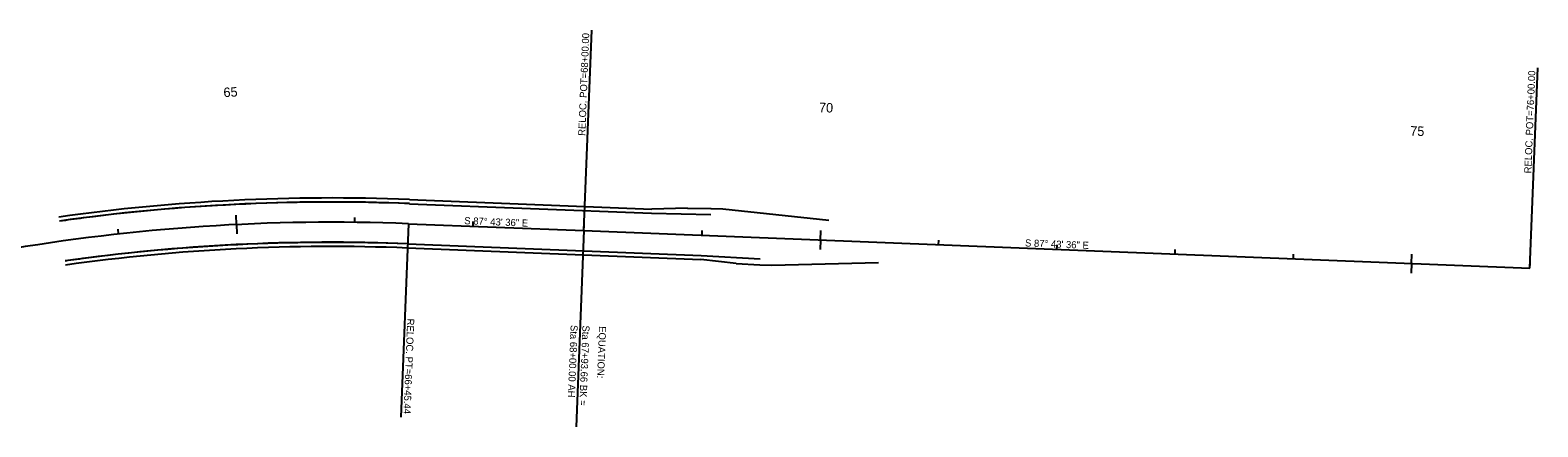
# Model space of a CAD drawing. Extents: x 1966701 to 1969286, y 1117441 to 1118086.
# Drawn here: x 1968012 to 1969286, y 1117751 to 1118086 of the extents above; entities that cross this region are included whole.
import ezdxf

# ---------------------------------------------------------------- set-up
doc = ezdxf.new("R2010")
doc.units = 0
for name, color, linetype in [('Level 19', 7, 'Continuous'), ('Level 27', 7, 'Continuous'), ('Level 35', 7, 'Continuous'), ('Level 39', 7, 'Continuous')]:
    doc.layers.add(name, color=color, linetype=linetype)

msp = doc.modelspace()

# ---------------------------------------------------------------- linework, layer by layer
at = {"layer": 'Level 19'}
for p, q in [((1968186.2, 1117921.9), (1968185.8, 1117929.9)), ((1968286.1, 1117923.7), (1968286.2, 1117927.7)), ((1968086.5, 1117913.9), (1968086, 1117917.9)), ((1968186.2, 1117921.9), (1968186.5, 1117913.9)), ((1968331.5, 1117922.6), (1968479.6, 1117916.7)), ((1968386.1, 1117920.4), (1968386.2, 1117924.4)), ((1968479.6, 1117916.7), (1968479.8, 1117920.7)), ((1968479.6, 1117916.7), (1969279, 1117884.9)), ((1968579.6, 1117912.7), (1968579.7, 1117916.7)), ((1968679.5, 1117908.7), (1968679.8, 1117916.7)), ((1968679.5, 1117908.7), (1968679.2, 1117900.8)), ((1968779.4, 1117904.8), (1968779.6, 1117908.8)), ((1968879.3, 1117900.8), (1968879.5, 1117904.8)), ((1968979.3, 1117896.8), (1968979.4, 1117900.8)), ((1969079.2, 1117892.9), (1969079.3, 1117896.9)), ((1969179.1, 1117888.9), (1969179.4, 1117896.9)), ((1969179.1, 1117888.9), (1969178.8, 1117880.9)), ((1969279, 1117884.9), (1969279.2, 1117888.9))]:
    msp.add_line(p, q, dxfattribs=at)
msp.add_arc((1968266.6, 1116286.8), 1637, 87.7266, 111.9958, dxfattribs=at)
at = {"layer": 'Level 27'}
for p, q in [((1968332.2, 1117939.5), (1968536.9, 1117931.4)), ((1968536.9, 1117931.4), (1968586.9, 1117930.4)), ((1968330.9, 1117905.6), (1968578.7, 1117895.7)), ((1968578.7, 1117895.7), (1968628.6, 1117892.8))]:
    msp.add_line(p, q, dxfattribs=at)
for radius, start, end in [(1654.1, 87.7266, 97.9969), (1654, 87.7266, 97.2969), (1654, 97.2969, 97.9969), (1620.1, 87.7266, 97.9969), (1620, 87.7266, 97.2969), (1620, 97.2969, 97.9969)]:
    msp.add_arc((1968266.6, 1116286.8), radius, start, end, dxfattribs=at)
at = {"layer": 'Level 35'}
for p, q in [((1968332.4, 1117943), (1968537, 1117934.9)), ((1968567.1, 1117935.8), (1968537, 1117934.9)), ((1968567.1, 1117935.8), (1968587, 1117935.4)), ((1968587.1, 1117935.4), (1968597.1, 1117935)), ((1968597.1, 1117935), (1968686.7, 1117925.5)), ((1968330.7, 1117902.1), (1968578.6, 1117892.2)), ((1968608.4, 1117888.9), (1968578.6, 1117892.2)), ((1968638.4, 1117887.4), (1968728.6, 1117889.8)), ((1968608.4, 1117888.9), (1968628.3, 1117887.8)), ((1968628.4, 1117887.8), (1968638.4, 1117887.4))]:
    msp.add_line(p, q, dxfattribs=at)
for radius in [1657.5, 1616.5]:
    msp.add_arc((1968266.6, 1116286.8), radius, 87.7266, 97.9969, dxfattribs=at)
at = {"layer": 'Level 39'}
for p, q in [((1968479.6, 1117916.7), (1968486.4, 1118086.1)), ((1969279, 1117884.9), (1969285.7, 1118054.4)), ((1968331.5, 1117922.6), (1968325.1, 1117759.1)), ((1968479.6, 1117916.7), (1968473.1, 1117750.9))]:
    msp.add_line(p, q, dxfattribs=at)

# ---------------------------------------------------------------- texts
at = {"layer": 'Level 19'}
for s, rotation, p in [('65', 2.8171, (1968175.3, 1118029.5)), ('70', 357.7266, (1968678.2, 1118016.9)), ('75', 357.7266, (1969177.8, 1117997.1))]:
    msp.add_text(s, height=8, rotation=rotation, dxfattribs=at).set_placement(p)
at = {"layer": 'Level 39'}
for s, rotation, p in [('RELOC. POT=68+00.00', 87.7266, (1968480.8, 1117996.7)), ('RELOC. POT=76+00.00', 87.7266, (1969280.2, 1117965)), ('S 87%%d 43\' 36" E', 357.7266, (1968378.5, 1117922.2)), ('S 87%%d 43\' 36" E', 357.7266, (1968852.3, 1117903.4)), ('RELOC. PT=66+45.44', 267.7266, (1968330.4, 1117842.5)), ('Sta 68+00.00 AH', 267.7266, (1968468.5, 1117837.1)), ('Sta 67+93.66 BK = ', 267.7266, (1968478.5, 1117836.7)), ('EQUATION:', 267.7266, (1968492.5, 1117836.1))]:
    msp.add_text(s, height=6, rotation=rotation, dxfattribs=at).set_placement(p)

doc.saveas('drawing.dxf')
